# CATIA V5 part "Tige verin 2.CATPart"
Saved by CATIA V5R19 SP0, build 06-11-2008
Part number: Tige verin 2
Bounding box of the stored display mesh (mm): x -44.746 to 80.254, y -7.954 to 7.954, z -7.954 to 7.954
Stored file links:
  G:\EU_thinkMotion\CFAO_2010\St2M_groupe2\St2M_groupe2\csayed\csayed\csayed\Tige verin 2.CATPart
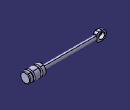
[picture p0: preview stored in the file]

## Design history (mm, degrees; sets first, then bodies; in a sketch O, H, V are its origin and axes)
Body1 (main body)
  Sketch1 on zx-plane, origin (0, 0, 0), H (-1, 0, 0), V (0, 0, 1)
    line L1 (-80.2536, 0) -> (-80.2536, 8)
    point P1 (-80.2536, 0)
    line L2 (-80.2536, 8) -> (-55.2536, 8)
    line L3 (-55.2536, 8) -> (-55.2536, 3)
    line L4 (-55.2536, 3) -> (29.7464, 3)
    line L5 (29.7464, 3) -> (29.7464, 0)
    point P6 (29.7464, 0)
    coincidence: P1 H, P6 H
    vertical: L1 V, L3 V, L5 V
    horizontal: L2 H, L4 H
  Shaft1: profile Sketch1, axis Sketch1.H, angle 360
  Sketch2 on zx-plane, origin (0, 0, 0), H (-1, 0, 0), V (0, 0, 1)
    line L1 (-75.2536, 9.6276) -> (-72.2536, 9.6276)
    line L2 (-72.2536, 9.6276) -> (-72.2536, 5)
    line L3 (-72.2536, 5) -> (-75.2536, 5)
    line L4 (-75.2536, 5) -> (-75.2536, 9.6276)
    reference projected line E1 (-80.2536, 8) -> (-80.2536, -8) from edge [face of Shaft1 from Sketch1.L1 | face of Shaft1 from Sketch1.L2]
    distance E1 L4 = 5
    horizontal: L1 H, L3 H
    vertical: L2 V, L4 V
  Groove1: profile Sketch2, axis Sketch2.H, angle 360
  Sketch3 on zx-plane, origin (0, 0, 0), H (-1, 0, 0), V (0, 0, 1)
    line L1 (-63.2536, 12.3358) -> (-60.2536, 12.3358)
    line L2 (-60.2536, 12.3358) -> (-60.2536, 5)
    line L3 (-60.2536, 5) -> (-63.2536, 5)
    line L4 (-63.2536, 5) -> (-63.2536, 12.3358)
    reference projected line E1 (-55.2536, 8) -> (-55.2536, -8) from edge [face of Shaft1 from Sketch1.L2 | face of Shaft1 from Sketch1.L3]
    reference projected line E2 through (0, 0) direction (1, 0) from axis of face of Shaft1 from Sketch1.L2
    distance L2 E1 = 5
    distance L3 E2 = 5
    horizontal: L1 H, L3 H
    vertical: L2 V, L4 V
  Groove2: profile Sketch3, axis Sketch3.H, angle 360
  Fillet1: radius 1, on face of Shaft1 from Sketch1.L1
  Sketch4 on face of Shaft1 from Sketch1.L5, origin (-29.7464, 0, 0), H (0, -1, 0), V (0, 0, 1)
    line L1 (-2.5, 7) -> (2.5, 7)
    line L2 (2.5, 7) -> (2.5, -7)
    line L3 (2.5, -7) -> (-2.5, -7)
    line L4 (-2.5, -7) -> (-2.5, 7)
    horizontal: L1 H, L3 H
    vertical: L2 V, L4 V
  Pad1: profile Sketch4, direction (-1, 0, 0), length 15
  Fillet2: radius 3, on edge [start face of Pad1 | face of Pad1 from Sketch4.L1]; edge [start face of Pad1 | face of Pad1 from Sketch4.L3]
  Sketch5 on face of Pad1 from Sketch4.L4, origin (0, 2.5, 0), H (-1, 0, 0), V (0, 0, 1)
    circle A1 centre (37.2464, 0) radius 5
    point P1 (37.2464, 0)
    reference projected line E1 through (0, 0) direction (1, 0) from axis of face of Shaft1 from Sketch1.L4
    reference projected line E2 (44.7464, 7) -> (44.7464, -7) from edge [face of Pad1 from Sketch4.L4 | end face of Pad1]
    distance P1 E1 = 0
    distance P1 E2 = 7.5
  Pocket1: profile Sketch5, direction (0, -1, 0), through (limit type 3)
  Fillet3: radius 7, on edge [face of Pad1 from Sketch4.L1 | end face of Pad1]
  Fillet4: radius 7, on edge [face of Pad1 from Sketch4.L3 | end face of Pad1]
